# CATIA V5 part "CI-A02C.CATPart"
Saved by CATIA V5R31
Part number: CI-A02C SEDIA SENZA BRACCIOLI
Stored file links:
  C:\Users\simone\Dropbox\3DTECH\Cassina - Catalogo Custom Interiors\MODELLI 3D\DEFINITIVI\CI-A02C SEDIA SENZA BRACCIOLI.CATPart

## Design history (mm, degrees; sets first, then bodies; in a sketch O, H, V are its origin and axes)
Body1 "Solido1" (main body)
  Solid1: solid without history
Body2 "Solido8"
  Solid2: solid without history
Body3 "Solido9"
  Solid3: solid without history
Body4 "Solido18"
  Solid4: solid without history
